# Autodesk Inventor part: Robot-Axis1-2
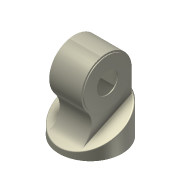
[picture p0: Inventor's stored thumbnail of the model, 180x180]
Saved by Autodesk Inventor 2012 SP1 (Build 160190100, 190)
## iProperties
Shininess: 21.0
Length Units: 11269
Angle Units: 11279
Time Units: 11290
Mass Units: 11283
Length Display Precision: 3
Angle Display Precision: 2
Created: 2001-08
Part Number: Robot-Axis1-2
Document SubType Name: ﾓﾃﾞﾘﾝｸﾞ
Designer: Administrator
Density: 1 g/cm^3
Material: Default
Density: 0.0
Volumn: 0.0
Area: 0.0
PropertySet Name: Model Information
Control State: 0
Master: False
Checked Out: False
Author: Administrator
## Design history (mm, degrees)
node "Center-Work Plane"
fillet "Chamfer" dims "d19" = 2
node "Sketch6"
sketch "Sketch7"
  geometry: C1 r 56 at (-128, 0); A1 r 60 centre (-128, 0) between (-128, 60) and (-89.273, -45.828) reference
  constraints: 1 centre point, 1 coincident
  dimensions: "d20" = 4 radial gap between concentric circles of A1 C1
extrude "Extrusion6" join sketch "Sketch7" distance "d21" = 2; taper "d22" = 0 deg
mirror "Mirror3"
shell "Shell1" dims "d25" = 2
sketch "Sketch10"
  geometry: C1 r 75 at (0, 0) reference
hole "Hole1" sketch "Sketch10" at (0, 0) diameter "d26" = 50; stored, may be unused: countersink angle "d30" = 82 deg, drill point angle "d32" = 118 deg; dims "d27" = 6, "d28" = 4, "d29" = 2, "d31" = 2
sketch "Sketch11"
  geometry: C1 r 56 at (0, 0) reference
hole "Hole2" sketch "Sketch11" at (0, 0) diameter "d33" = 50; stored, may be unused: countersink angle "d37" = 82 deg, drill point angle "d39" = 118 deg; dims "d34" = 6, "d35" = 4, "d36" = 2, "d38" = 2
body "Solid1"
sketch "ｽｹｯﾁ1"
  geometry: C1 r 75 at (0, 0)
  constraints: 1 centre point
  dimensions: "d0" = 150 diameter of C1
extrude "Extrusion1" new body sketch "ｽｹｯﾁ1" distance "d1" = 120; taper "d2" = 0 deg
sketch "ｽｹｯﾁ3"
  geometry: L1 (-75, 0)-(-75, 120) reference; L2 (75, 0)-(75, 120) reference; L3 (-75, 0)-(75, 0) reference; L4 (-75, 13)-(75, 82.946)
  constraints: 2 end point, 2 point on line
  dimensions: "d7" = 13 distance from line of L3 L4.start; "d8" = 25 deg angle of L3 L4
extrude "Extrusion3" sketch "ｽｹｯﾁ3" stored distance "d9" = 155; taper "d10" = 0 deg
sketch "Sketch4"
  geometry: L1 (0, 0)-(0, 128); L2 (-60, 128)-(60, 128); L3 (75, 82.946)-(-75, 13) reference; L4 (-75, 0)-(75, 0) reference; L5 (60, 128)-(60, 75.952); L6 (-61.181, 19.444)-(60, 75.952); A1 r 60 centre (0, 128) between (-60, 128) and (60, 128); A2 r 45 centre (-80.199, 60.228) between (-61.181, 19.444) and (-45.828, 89.273); 1 further point
  constraints: 8 end point, 5 point on circle, 4 tangent, 3 point on line, 2 centre point, 2 perpendicular, 1 coincident, 1 midpoint, 1 vertical, 1 other
  dimensions: "d11" = 120 diameter of A1; "d12" = 90 diameter of A2; "d13" = 128 distance between parallel lines of L4 L2
extrude "Extrusion4" join sketch "Sketch4" stored distance "d14" = 76; taper "d15" = 0 deg
